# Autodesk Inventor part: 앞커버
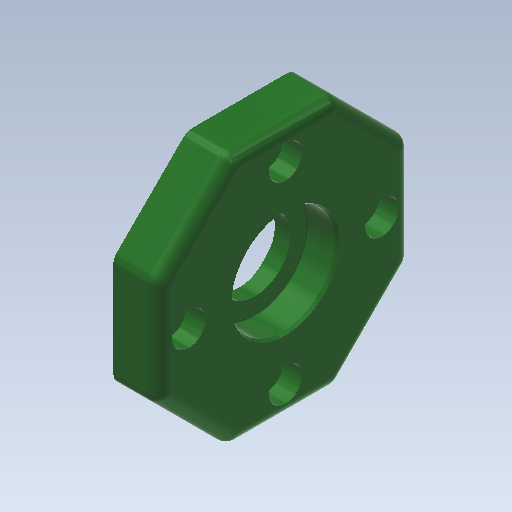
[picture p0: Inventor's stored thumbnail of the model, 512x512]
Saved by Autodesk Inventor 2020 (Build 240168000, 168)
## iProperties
Created: 2015-11
Part Number: 앞커버
Material: 알루미늄 6061
Document SubType Name: Modeling
Designer: mduedu
Density: 1 g/cm^3
Appearance: 매끄러움 - 짙은 산림 녹색
Author: mduedu
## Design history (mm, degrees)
sketch "스케치5" dims "d66" = 60
  geometry: L1 (12.426, 30)-(30, 12.426); L2 (30, 12.426)-(30, -12.426); L3 (30, -12.426)-(12.426, -30); L4 (12.426, -30)-(-12.426, -30); L5 (-12.426, -30)-(-30, -12.426); L6 (-30, -12.426)-(-30, 12.426); L7 (-30, 12.426)-(-12.426, 30); L8 (-12.426, 30)-(12.426, 30); 4 further points
  constraints: 16 end point, 2 coincident, 2 vertical alignment, 1 midpoint, 19 other
extrude "돌출2" new body sketch "스케치5" distance "d67" = 11; taper "d68" = 0 deg
sketch "스케치6"
  geometry: C1 r 16 at (0, 0); 1 further point
  constraints: 1 centre point, 1 coincident
  dimensions: "d69" = 32 diameter of C1
extrude "돌출3" join sketch "스케치6" distance "d70" = 3; taper "d71" = 0 deg
hole "구멍7" diameter "d98" = 25; stored, may be unused: countersink angle "d102" = 90 deg, drill point angle "d104" = 0 deg; dims "d96" = 10, "d97" = 10, "d99" = 6, "d100" = 4, "d101" = 2, "d103" = 3
hole "구멍8" diameter "d107" = 25; stored, may be unused: countersink angle "d111" = 90 deg, drill point angle "d113" = 0 deg; dims "d108" = 6, "d109" = 4, "d110" = 2, "d112" = 7.3, "d143" = 10, "d144" = 10
hole "구멍9" diameter "d116" = 17; stored, may be unused: countersink angle "d120" = 90 deg, drill point angle "d122" = 0 deg; dims "d114" = 10, "d115" = 10, "d117" = 6, "d118" = 4, "d119" = 2, "d121" = 7.7
chamfer "모따기2" distance "d123" = 0.7; stored, may be unused: second distance "d124" = 2, angle "d125" = 30 deg
fillet "모깎기11" dims "d126" = 0.3
fillet "모깎기12" dims "d127" = 3
fillet "모깎기13" dims "d128" = 3
fillet "모깎기14" dims "d129" = 3
fillet "모깎기15" dims "d130" = 0.3
sketch "스케치8" dims "d131" = 46
  geometry: 3 further points
  constraints: 2 vertical alignment, 1 coincident, 2 other
hole "구멍10" sketch "스케치8" at (0, 23) diameter "d132" = 4.5; stored, may be unused: countersink angle "d136" = 90 deg, drill point angle "d138" = 0 deg; dims "d133" = 6, "d134" = 8, "d135" = 4.6, "d137" = 7.7
node "솔리드2"
pattern_circular "원형 패턴4" dims angle "d140" = 360 deg
